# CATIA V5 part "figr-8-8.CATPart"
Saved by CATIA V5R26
Part number: Part1
Bounding box of the stored display mesh (mm): x 4.549 to 89.781, y -52.238 to 26.36, z 54 to 147.773
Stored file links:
  D:\_Deepak\CATIA\CATIA V5-6R2016_Deepak\Resources\Part files\Partfiles\c08_catia_v5_6r2016_prt\figr-8-8.CATPart
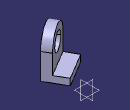
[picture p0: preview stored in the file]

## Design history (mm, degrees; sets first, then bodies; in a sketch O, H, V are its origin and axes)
Body1 (main body)
  Sketch1 on yz-plane, origin (0, 0, 0), H (0, 1, 0), V (0, 0, 1)
    point P1 (-104.4861, 0)
    line L1 (-104.4861, 0) -> (-104.4861, 44.267)
    arc A1 centre (-69.7903, 44.267) radius 34.6958 from (-104.4861, 44.267) to (-35.0946, 44.267) cw
    line L2 (-35.0946, 44.267) -> (-35.0946, 0)
    point P5 (-35.0946, 0)
    line L3 (-35.0946, 0) -> (-104.4861, 0)
    circle A2 centre (-69.7903, 44.267) radius 19.5413
    coincidence: P1 H, P5 H
    vertical: L1 V
    tangency: A1 L1, L2 A1
    horizontal: L3 H
  Pad1: profile Sketch1, direction (1, 0, 0), length 20
  Sketch2 on face of Pad1, origin (0, 0, 0), H (0, -1, 0), V (0, 0, 1)
    point P1 (35.0946, 0)
    line L1 (35.0946, 0) -> (104.4861, 0)
    line L2 (104.4861, 0) -> (104.4861, -15)
    line L3 (104.4861, -15) -> (35.0946, -15)
    line L4 (35.0946, -15) -> (35.0946, 0)
    reference projected line E1 (35.0946, 0) -> (35.0946, 44.267) from edge [face of Pad1 | face of Pad1]
    reference projected line E2 (104.4861, 44.267) -> (104.4861, 0) from edge [face of Pad1 | face of Pad1]
    distance L3 L1 = 15
    coincidence: P1 H, L4 E1, L2 E2
    horizontal: L1 H, L3 H
    vertical: L2 V, L4 V
  Pad2: profile Sketch2, direction (1, 0, 0), length 50
  Translate1: ToTransfor Pad2, Direction xy-plane, Length 69
  Rotate1: ToTransfor Translate1, Axis edge, Angle 121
